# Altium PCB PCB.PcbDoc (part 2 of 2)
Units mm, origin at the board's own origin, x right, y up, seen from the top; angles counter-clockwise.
Board outline 68.58 x 53.34 mm, 2 copper layers (TOP, BOTTOM), stack 1.636 mm thick; 84 components, 64 nets, 302 pads, 163 vias.
Unrouted connection lines stored in the file: 1.
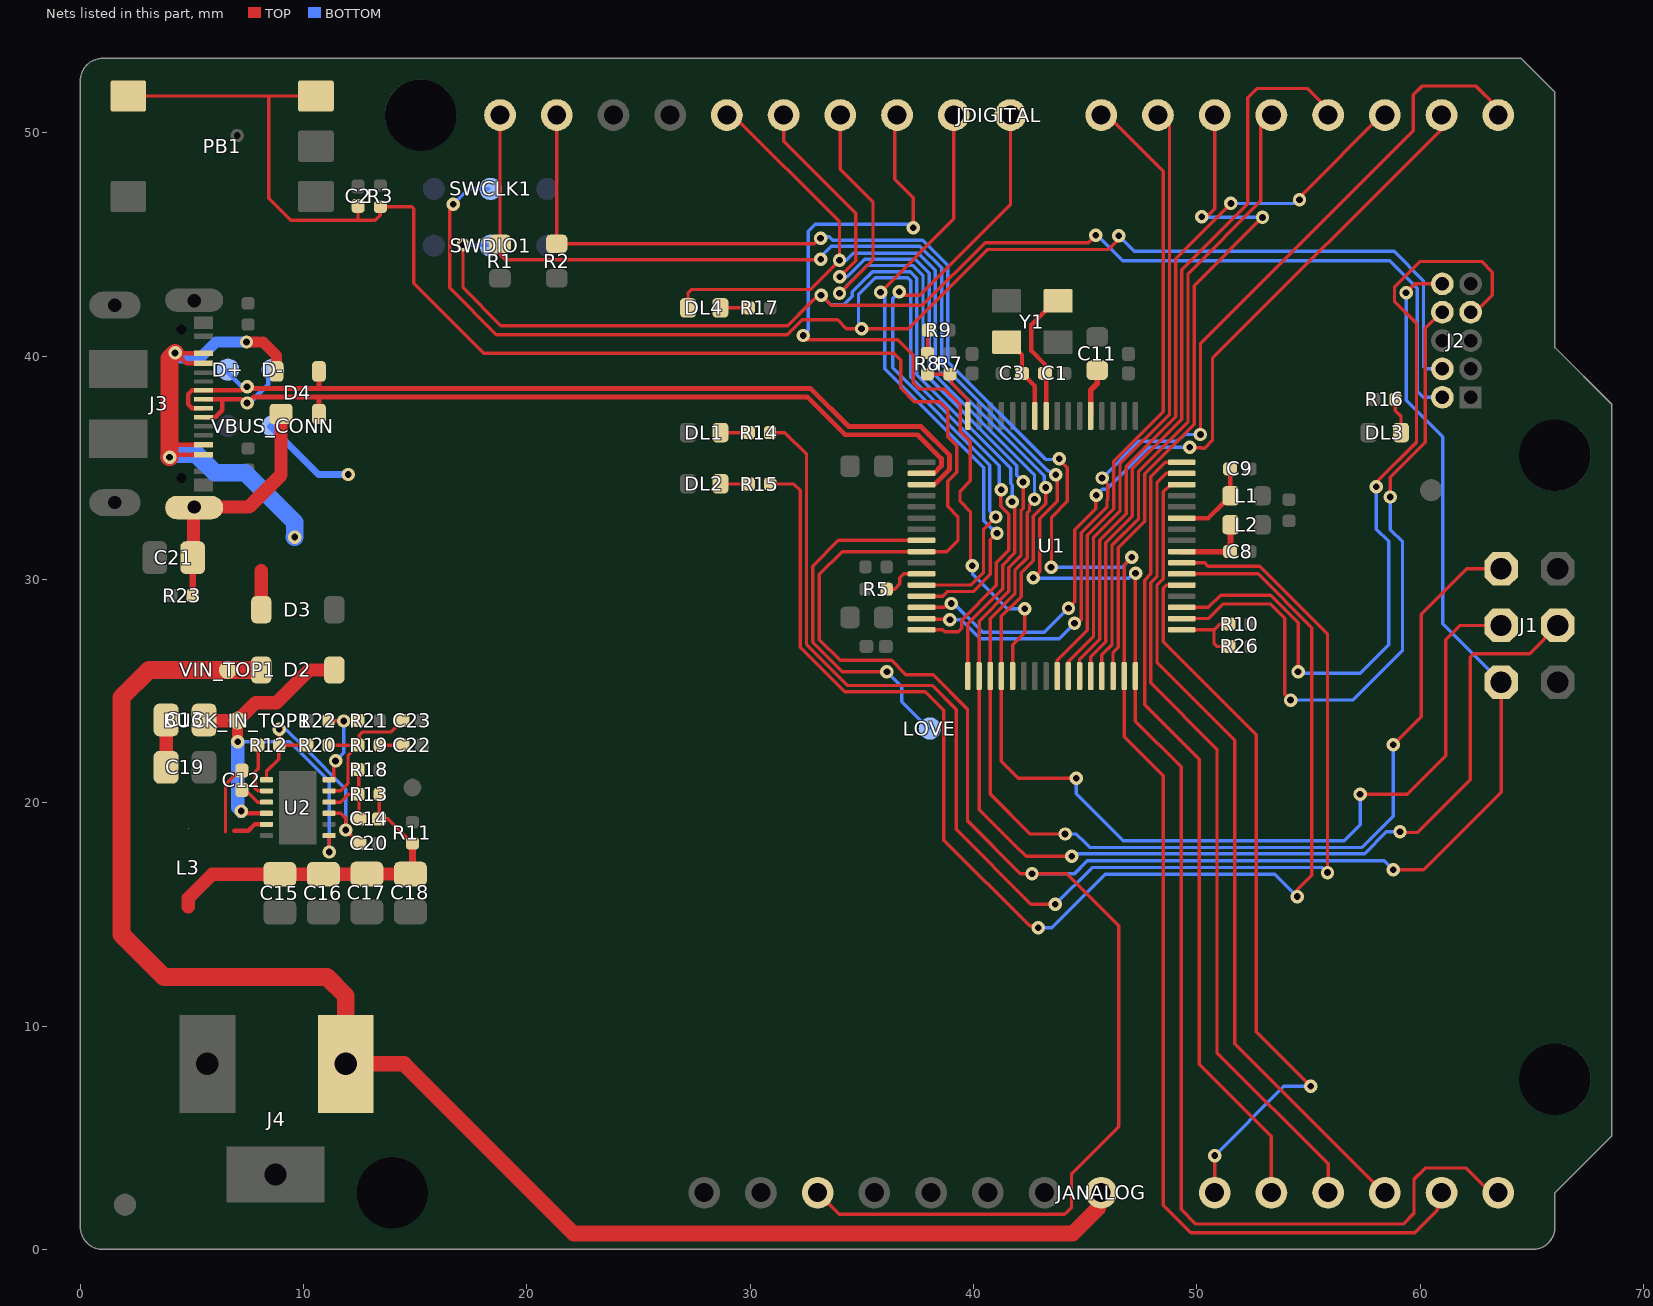
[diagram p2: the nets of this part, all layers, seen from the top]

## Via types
v1: diameter 0.6, hole 0.3, TOP to BOTTOM, tented both sides, 163 vias

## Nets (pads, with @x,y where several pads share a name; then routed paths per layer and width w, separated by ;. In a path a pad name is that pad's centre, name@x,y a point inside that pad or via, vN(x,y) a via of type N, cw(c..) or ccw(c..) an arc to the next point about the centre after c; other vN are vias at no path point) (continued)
NetBUCK_IN_TOP1_X: BUCK_IN_TOP1.X C13.2 D2.C U2.4 U2.7 | length 20.8
  TOP w0.15: U2.7@11.138,18.532 11.143,18.527 v1(11.143,17.796)
  TOP w0.2: v1(7.202,19.629) 7.299,19.532 U2.4@8.338,19.532
  TOP w0.5: BUCK_IN_TOP1.X@7.038,23.682 7.045,23.675 7.045,22.742 v1(7.052,22.735)
  TOP w0.6: C13.2@5.567,23.682 BUCK_IN_TOP1.X@6.984,23.682 ; BUCK_IN_TOP1.X@7.038,23.682 7.844,24.488 8.787,24.488 10.246,25.947 D2.C@11.373,25.947
  BOTTOM w0.15: v1(7.052,22.735) 9.371,22.735 11.143,20.964 v1(11.143,17.796) v1@11.056,17.71
  BOTTOM w0.6: v1(7.052,22.735) 7.052,19.779 v1(7.202,19.629)
NetC1_1: C1.1 U1.9 Y1.3 | length 5.9
  TOP w0.2: U1.9@43.25,37.325 43.25,39.184 C1.1@43.203,39.231 43.203,39.631 42.596,40.238 42.596,41.409 Y1.3@43.663,42.476
NetC3_1: C3.1 U1.10 Y1.1 | length 3.9
  TOP w0.2: Y1.1@41.487,40.626 41.612,40.626 42.173,40.066 C3.1@42.173,39.231 42.75,38.654 U1.10@42.75,37.325
NetC8_2: C8.2 L2.2 U1.56 | length 3.4
  TOP w0.25: U1.56@49.325,31.25 C8.2@51.493,31.25 ; C8.2@51.51,31.258 51.51,32.443 L2.2@51.518,32.45
NetC11_2: C11.2 U1.5 | length 2.2
  TOP w0.25: U1.5@45.25,37.325 45.25,38.478 45.538,38.766 C11.2@45.538,39.366
NetC12_1: C12.1 L3.1 U2.5 | length 4.4
  TOP w0.15: 6.5,18.7 6.5,20.804 6.945,21.249 7.029,21.249 7.038,21.258 C12.1@7.038,21.286
  TOP w0.2: 6.899,18.753 7.525,18.753 7.804,19.032 U2.5@8.338,19.032
NetC12_2: C12.2 U2.3 | length 1.5
  TOP w0.15: C12.2@7.038,20.572 7.411,20.572 7.951,20.032 U2.3@8.338,20.032
NetC13_1: C13.1 C19.2 | length 2.1
  TOP w0.6: C19.2@3.841,21.591 C13.1@3.841,23.708
NetC14_1: C14.1 R13.2 R18.2 U2.10 | length 3.7
  TOP w0.15: U2.10@11.138,20.032 11.656,20.032 12.005,20.381 12.462,20.381 R13.2@12.463,20.382 ; R18.2@12.463,21.482 R13.2@12.463,20.382 ; C14.1@12.503,19.282 12.483,19.302 12.483,20.362 R13.2@12.463,20.382
NetC14_2: C14.2 C15.2 C16.2 C17.2 C18.2 L3.2 R11.1 R13.1 | length 15.4
  TOP w0.15: C14.2@13.373,19.282 13.763,19.282 14.863,18.182 R11.1@14.873,18.182 ; C14.2@13.393,19.302 13.393,20.362 R13.1@13.413,20.382
  TOP w0.3: C18.2@14.784,16.812 14.873,16.9 R11.1@14.873,18.182
  TOP w0.5: C18.2@14.403,16.812 14.564,16.812 C18.2@14.869,17.117
  TOP w0.6: L3.2@4.836,15.349 4.836,15.721 5.912,16.797 8.501,16.797 8.509,16.804 10.886,16.804 C17.2@12.434,16.804 ; C17.2@12.434,16.812 C18.2@14.384,16.812
NetC20_1: C20.1 R12.2 R20.2 U2.1 U2.9 | length 12.2
  TOP w0.15: U2.1@8.338,21.032 8.338,21.408 8.886,21.956 8.886,22.555 R12.2@8.913,22.582 ; v1(8.908,23.294) 8.91,23.291 8.91,22.79 R12.2@8.908,22.787 ; R20.2@10.163,22.582 R12.2@9.113,22.582 ; U2.9@11.138,19.532 11.664,19.532 11.883,19.313 v1(11.883,18.781) 12.482,18.182 C20.1@12.503,18.182 ; R12.2@8.908,22.787 R12.2@9.113,22.582 ; R12.2@8.908,22.787 8.908,22.582 R12.2@8.913,22.582 ; R12.2@8.913,22.582 R12.2@9.113,22.582
  BOTTOM w0.15: v1(8.908,23.294) 9.204,23.294 10.066,22.432 11.883,20.616 v1(11.883,18.781)
NetC22_2: C22.2 R19.1 | length 1
  TOP w0.15: R19.1@13.413,22.582 C22.2@14.438,22.582
NetC23_2: C23.2 R19.2 R20.1 U2.11 | length 6.9
  TOP w0.15: R20.1@11.113,22.582 R19.2@12.463,22.582 ; U2.11@11.138,20.532 11.656,20.532 11.986,20.862 11.986,22.105 12.49,22.609 12.49,23.034 12.625,23.169 13.9,23.169 14.413,23.682 C23.2@14.438,23.682
NetDL1_C: DL1.C R14.2 | length 1.3
  TOP w0.15: DL1.C@28.665,36.576 R14.2@29.938,36.576
NetDL2_C: DL2.C R15.2 | length 1.3
  TOP w0.15: DL2.C@28.665,34.29 28.679,34.276 R15.2@29.945,34.276
NetDL3_C: DL3.C R16.2 | length 1.6
  TOP w0.15: R16.2@58.895,38.066 58.895,37.551 59.145,37.301 DL3.C@59.145,36.576
NetDL4_C: DL4.C R17.2 | length 1.3
  TOP w0.15: DL4.C@28.665,42.164 R17.2@29.945,42.164
NetR5_2: R5.2 U1.27 | length 2
  TOP w0.15: R5.2@36.113,29.566 36.463,29.566 36.699,29.802 36.699,30.079 36.87,30.25 U1.27@37.675,30.25
NetR7_1: R7.1 R8.2 U1.16 | length 3.2
  TOP w0.15: R8.2@37.938,39.191 R7.1@38.938,39.191 39.016,39.112 39.016,38.779 39.744,38.051 39.744,37.331 U1.16@39.75,37.325
NetR8_1: R8.1 R9.2 | length 1
  TOP w0.15: R8.1@37.938,40.141 37.95,40.154 37.95,41.154 R9.2@37.963,41.166
NetR10_1: R10.1 R26.2 U1.49 | length 3.6
  TOP w0.15: U1.49@49.325,27.75 50.773,27.75 ; R26.2@51.453,27 50.9,27 50.773,27.127 50.773,27.75 ; R10.1@51.453,28 51.023,28 50.773,27.75
NetR12_1: R12.1 U2.2 | length 2.5
  TOP w0.15: R12.1@7.963,22.582 7.963,21.525 7.834,21.396 7.834,20.635 7.937,20.532 U2.2@8.338,20.532
NetR21_2: R21.2 R22.2 U2.12 | length 4.1
  TOP w0.15: R22.2@11.113,23.682 11.123,23.671 11.781,23.671 v1(11.791,23.661) 11.802,23.671 12.452,23.671 R21.2@12.463,23.682 ; U2.12@11.138,21.032 11.304,21.032 11.344,21.072 v1@11.344,21.665
  BOTTOM w0.15: v1(11.432,21.875) 11.791,22.234 v1(11.791,23.661)
P000_AN00_AMP+_1: JANALOG.10 U1.64 | length 36.2
  TOP w0.15: U1.64@49.325,35.25 48.595,35.25 47.944,34.599 47.944,32.767 47.944,30.257 47.661,29.975 47.661,24.386 50.103,21.944 50.103,8.301 53.34,5.064 JANALOG.10@53.34,2.54
P001_AN01_AMP-_1: JANALOG.11 U1.63 | length 36.5
  TOP w0.15: U1.63@49.325,34.75 48.625,34.75 48.221,34.346 48.221,32.653 48.221,30.142 47.938,29.86 47.938,25.372 50.903,22.407 50.903,8.807 55.88,3.83 JANALOG.11@55.88,2.54
P002_AN02_AMPO_1: JANALOG.12 U1.62 | length 36.7
  TOP w0.15: U1.62@49.325,34.25 48.825,34.25 48.498,33.923 48.498,32.422 48.498,30.028 48.215,29.745 48.215,26.295 51.703,22.807 51.703,9.207 58.37,2.54 JANALOG.12@58.42,2.54
P012_1: R14.1 U1.55 | length 61.2
  TOP w0.15: R14.1@30.888,36.576 31.549,36.576 32.523,35.602 32.523,27.085 34.353,25.255 38.143,25.255 39.221,24.177 39.221,18.804 42.574,15.451 v1(43.668,15.451) ; U1.55@49.325,30.75 50.35,30.75 50.5,30.6 52.813,30.6 55.852,27.561 v1(55.852,16.874)
  BOTTOM w0.15: v1(43.668,15.451) 45.317,17.1 55.627,17.1 v1(55.852,16.874)
P013_1: R15.1 U1.54 | length 59.9
  TOP w0.15: R15.1@30.895,34.276 31.958,34.276 32.246,33.988 32.246,26.971 34.238,24.978 37.847,24.978 38.673,24.152 38.673,18.327 42.514,14.486 42.814,14.486 v1(42.9,14.4) ; U1.54@49.325,30.25 52.743,30.25 55.15,27.843 55.15,16.75 54.5,16.1 v1(54.5,15.8)
  BOTTOM w0.15: v1(42.9,14.4) 43.501,14.4 45.901,16.8 53.5,16.8 v1(54.5,15.8)
P014_AN09_DAC_1: JANALOG.9 U1.53 | length 33.2
  TOP w0.15: U1.53@49.325,29.75 48.625,29.75 48.492,29.617 48.492,27.218 52.655,23.055 52.655,9.745 v1(55.1,7.3) ; JANALOG.9@50.8,2.54 v1(50.8,4.2)
  BOTTOM w0.15: v1(50.8,4.2) 53.9,7.3 v1(55.1,7.3)
P100_AN22_SCL_1: JANALOG.14 JDIGITAL.18 R1.1 U1.48 | length 94.6
  TOP w0.15: JDIGITAL.18@18.796,51.054 R1.1@18.796,45.034 18.796,44.549 19.03,44.315 32.903,44.315 33.038,44.45 33.043,44.45 v1(33.156,44.337) ; v1(42.68,30.074) 42.96,30.354 42.96,32.724 43.744,33.508 43.744,34.633 v1(43.688,34.688) ; v1(47.259,30.282) 47.25,30.273 U1.48@47.25,25.675 47.25,23.66 49.303,21.607 49.303,1.793 49.961,1.135 59.239,1.135 59.727,1.623 59.727,3.145 60.226,3.644 62.062,3.644 63.166,2.54 JANALOG.14@63.5,2.54
  BOTTOM w0.15: v1(33.156,44.337) 33.156,44.446 33.633,44.923 37.602,44.923 38.571,43.954 38.571,43.382 38.571,39.636 43.332,34.875 43.38,34.875 43.566,34.688 v1(43.688,34.688) ; v1(42.68,30.074) 42.703,30.051 46.959,30.051 47.19,30.282 v1(47.259,30.282)
P101_AN21_SDA_1: JANALOG.13 JDIGITAL.17 R2.1 U1.47 | length 88.4
  TOP w0.15: JDIGITAL.17@21.336,51.054 R2.1@21.336,45.034 32.872,45.034 33.124,45.286 v1(33.15,45.286) ; v1(43.474,30.553) 43.494,30.573 43.494,32.788 44.201,33.495 44.201,35.002 43.834,35.37 v1(43.834,35.401) ; v1(47.09,30.992) 46.757,30.658 46.757,26.682 46.75,26.675 U1.47@46.75,25.675 46.75,22.96 48.503,21.207 48.503,1.966 49.719,0.75 59.76,0.75 60.764,1.754 60.764,2.344 JANALOG.13@60.96,2.54
  BOTTOM w0.15: v1(33.15,45.286) 33.215,45.35 33.55,45.35 33.7,45.2 37.716,45.2 38.848,44.069 38.848,43.497 38.848,39.751 43.224,35.375 43.808,35.375 v1(43.834,35.401) ; v1(43.474,30.553) 46.651,30.553 v1(47.09,30.992)
P102_SPI0_RSPCK_GPT2_B_CAN0_RX_1: JDIGITAL.6 U1.46 | length 31.2
  TOP w0.15: U1.46@46.25,25.675 46.25,26.734 46.48,26.964 46.48,31.411 47.667,32.598 47.667,32.882 47.667,34.728 49.886,36.947 49.886,43.16 v1(52.941,46.215) ; v1(50.228,46.241) 50.314,46.327 50.527,46.327 50.8,46.6 JDIGITAL.6@50.8,51.054
  BOTTOM w0.15: v1(50.228,46.241) 50.24,46.228 52.928,46.228 v1(52.941,46.215)
P103_SPI0_SSL_GPT2_A_CAN0_TX_1: JDIGITAL.5 U1.45 | length 28.4
  TOP w0.15: U1.45@45.75,25.675 45.75,26.626 46.203,27.079 46.203,31.526 47.39,32.713 47.39,32.997 47.39,34.843 49.609,37.062 49.609,43.7 52.865,46.956 52.865,48.614 52.865,50.417 JDIGITAL.5@53.34,50.892
P104_IRQ01_GPT1_B_1: JDIGITAL.4 U1.44 | length 33
  TOP w0.15: U1.44@45.25,25.675 45.25,26.541 45.926,27.217 45.926,31.641 47.113,32.828 47.113,33.111 47.113,34.957 49.332,37.176 49.332,43.879 52.289,46.836 52.289,51.575 52.705,51.99 54.944,51.99 JDIGITAL.4@55.88,51.054
P105_IRQ00_GPT1_A_1: JDIGITAL.3 U1.43 | length 32.7
  TOP w0.15: U1.43@44.75,25.675 44.75,26.433 45.649,27.331 45.649,31.755 46.836,32.943 46.836,33.226 46.836,35.072 49.055,37.291 49.055,44.359 51.528,46.831 v1(51.528,46.841) ; v1(54.6,47) 54.6,47.117 58.42,50.937 JDIGITAL.3@58.42,51.054
  BOTTOM w0.15: v1(51.528,46.841) 54.319,46.841 54.478,47 v1(54.6,47)
P106_GPT0_B_1: JDIGITAL.7 U1.42 | length 27.4
  TOP w0.15: U1.42@44.25,25.675 44.25,26.324 45.372,27.446 45.372,31.87 46.559,33.057 46.559,33.341 46.559,35.187 48.778,37.406 48.778,50.46 JDIGITAL.7@48.26,50.978
P107_GPT0_A_1: JDIGITAL.8 U1.41 | length 28.5
  TOP w0.15: U1.41@43.75,25.675 43.75,26.38 45.095,27.725 45.095,31.985 46.282,33.172 46.282,33.456 ; JDIGITAL.8@45.72,51.054 48.501,48.273 48.501,37.521 46.282,35.302 46.282,33.456
P108_SWDIO_1: J2.2 SWDIO1.X U1.33 | length 81.2
  TOP w0.15: v1(17.14,44.99) 17.14,43.064 18.838,41.366 31.677,41.366 32.604,42.293 33.042,42.731 v1(33.173,42.731) 33.631,42.274 34.422,42.274 37.714,42.274 40.516,45.076 45.142,45.076 v1(45.481,45.415) ; U1.33@39.75,25.675 39.75,28.028 41.303,29.581 41.303,30.643 41.852,31.192 41.852,33.238 41.727,33.363 v1(41.727,33.485)
  BOTTOM w0.15: v1(17.14,44.99) 17.156,44.974 18.272,44.974 SWDIO1.X@18.288,44.958 ; v1(33.173,42.731) 33.603,42.301 34.186,42.301 34.575,42.69 34.575,42.883 34.883,43.192 35.477,43.785 35.883,43.785 36.601,43.785 37.172,43.785 37.463,43.495 37.463,42.923 37.463,39.178 41.666,34.974 41.666,34.302 41.739,34.23 41.739,33.497 v1(41.727,33.485) ; v1(45.481,45.415) 45.546,45.415 45.596,45.364 46.687,44.274 58.649,44.274 59.874,43.048 59.874,38.429 60.144,38.16 J2.2@60.995,38.16
P109_SCI9_TXD_1: J1.4 JDIGITAL.12 U1.34 | length 74.8
  TOP w0.15: v1(34,42.825) 35.5,44.325 35.5,46.9 34.036,48.364 JDIGITAL.12@34.036,51.054 ; v1(42.221,34.369) 42.229,34.361 42.229,33.196 42.129,33.097 42.129,31.077 41.58,30.529 41.58,29.466 40.25,28.136 U1.34@40.25,25.675 40.25,19.694 41.204,18.74 41.844,18.1 41.853,18.1 42.353,17.6 v1(44.4,17.6) ; v1(59.1,18.7) 59.132,18.668 59.882,18.668 62.239,21.025 62.239,26.507 62.412,26.68 64.907,26.68 J1.4@66.167,27.94
  BOTTOM w0.15: v1(34,42.825) 34.644,43.469 35.237,44.062 35.998,44.062 36.715,44.062 37.287,44.062 37.74,43.61 37.74,43.038 37.74,39.292 41.943,35.089 41.943,34.659 42.221,34.381 v1(42.221,34.369) ; v1(44.4,17.6) 44.559,17.759 44.595,17.723 56.227,17.723 57.515,17.723 58.492,18.7 v1(59.1,18.7)
P110_SCI9_RXD_1: J1.1 JDIGITAL.13 U1.35 | length 73.4
  TOP w0.15: JDIGITAL.13@31.496,51.054 31.496,49.628 34.728,46.396 34.728,44.27 v1(34.013,43.555) ; v1(42.731,33.596) 42.731,33.516 42.506,33.291 42.506,33.081 42.406,32.982 42.406,30.963 41.857,30.414 41.857,29.351 40.75,28.244 U1.35@40.75,25.675 40.75,20.394 42.544,18.6 v1(44.1,18.6) ; v1(58.8,22.6) 60.052,23.852 60.052,28.452 62.08,30.48 J1.1@63.627,30.48
  BOTTOM w0.15: v1(34.013,43.555) 34.338,43.555 34.529,43.746 35.123,44.339 36.112,44.339 36.83,44.339 37.402,44.339 38.017,43.724 38.017,43.153 38.017,39.407 42.731,34.693 v1(42.731,33.596) ; v1(44.1,18.6) 44.6,18.6 45,18.2 45.01,18.2 45.21,18 57.4,18 58.8,19.4 v1(58.8,22.6)
P111_GPT3_A_1: DL4.A J1.3 JDIGITAL.14 U1.36 | length 78.6
  TOP w0.15: DL4.A@27.215,42.164 27.215,42.843 27.357,42.985 32.685,42.985 v1(34,44.3) 34,46.01 29.199,50.811 JDIGITAL.14@28.956,51.054 ; v1(43.233,34.121) 43.233,33.389 42.683,32.839 42.683,30.848 42.134,30.299 42.134,29.237 41.25,28.352 U1.36@41.25,25.675 41.25,21.85 42,21.1 v1(44.6,21.1) ; v1(57.313,20.376) 59.426,20.376 61.156,22.106 61.156,27.306 61.79,27.94 J1.3@63.627,27.94
  BOTTOM w0.15: v1(34,44.3) 34.3,44.3 34.616,44.616 35.132,44.616 36.227,44.616 36.945,44.616 37.516,44.616 38.294,43.839 38.294,43.267 38.294,39.522 43.173,34.642 43.173,34.182 v1(43.233,34.121) ; v1(44.6,21.1) 44.6,20.4 46.7,18.3 56.6,18.3 57.313,19.013 v1(57.313,20.376)
P112_GPT3_B_1: JDIGITAL.11 U1.37 | length 38.7
  TOP w0.15: v1(32.379,40.928) 32.575,40.732 36.614,40.732 37.3,40.046 37.3,38.8 37.569,38.531 38.699,38.531 39.405,37.825 39.405,36.612 39.857,36.16 39.857,34.413 39.396,33.953 39.396,33.504 39.863,33.037 39.863,30.921 39.863,30.7 v1(39.949,30.614) ; JDIGITAL.11@36.478,50.956 36.478,47.922 37.297,47.103 v1(37.297,45.753) ; U1.37@41.75,25.675 41.75,27.075 42.3,27.625 v1(42.3,28.692)
  BOTTOM w0.15: v1(32.379,40.928) 32.6,41.149 32.6,45.605 32.908,45.913 37.137,45.913 v1(37.297,45.753) ; v1(39.949,30.614) 39.971,30.592 39.971,30.239 41.517,28.692 v1(42.3,28.692)
P204_1: LOVE.X U1.24 | length 16
  TOP w0.15: v1(36.123,25.874) 34.126,25.874 32.8,27.2 32.8,30.6 33.95,31.75 U1.24@37.675,31.75
  BOTTOM w0.15: v1(36.123,25.874) 36.792,25.204 36.792,24.535 38.001,23.326 LOVE.X@38.045,23.326
P300_SWCLK_1: J2.4 SWCLK1.X U1.32 | length 82.8
  TOP w0.15: v1(16.7,46.8) 16.54,46.64 16.54,43.064 18.638,40.966 31.669,40.966 32.329,41.626 33.912,41.626 34.304,41.234 v1(34.987,41.234) 37.074,41.234 40.616,44.776 46.044,44.776 46.5,45.232 v1(46.5,45.4) ; U1.32@37.675,27.75 38.615,27.75 38.71,27.655 39.316,27.655 39.473,27.812 39.473,28.179 41.026,29.733 41.026,30.758 41.575,31.307 41.575,32.926 41.225,33.277 41.225,34.01 v1(41.237,34.022)
  BOTTOM w0.15: v1(16.7,46.8) 17.394,47.494 18.284,47.494 SWCLK1.X@18.288,47.498 ; v1(34.987,41.234) 34.852,41.369 34.852,42.769 35.591,43.508 37.058,43.508 37.186,43.38 37.186,39.063 41.16,35.088 41.16,34.098 v1(41.237,34.022) ; v1(46.5,45.4) 47.202,44.698 58.833,44.698 60.151,43.379 60.151,39.549 60.27,39.43 J2.4@60.995,39.43 ; J2.4@61.093,39.665 61.126,39.665 J2.4@61.361,39.43
P301_SCI2_RXD_1: JDIGITAL.1 U1.31 | length 43.4
  TOP w0.15: U1.31@37.675,28.25 37.703,28.222 38.917,28.222 v1(38.945,28.195) ; v1(44.524,28.041) 44.658,28.041 44.818,28.201 44.818,32.1 45.98,33.262 45.98,33.546 46.005,33.57 46.005,34.26 45.758,34.508 v1(45.758,34.543) ; v1(50.163,36.491) 50.163,40.563 59.7,50.1 59.7,51.7 60.1,52.1 62.5,52.1 JDIGITAL.1@63.4,51.2
  BOTTOM w0.15: v1(38.945,28.195) 39.46,28.195 40.302,27.354 43.837,27.354 v1(44.524,28.041) ; v1(45.758,34.543) 47.409,36.195 49.134,36.195 49.43,36.491 v1(50.163,36.491)
P302_SCI2_TXD_1: JDIGITAL.2 U1.30 | length 38.5
  TOP w0.15: U1.30@37.675,28.75 38.703,28.75 38.878,28.925 v1(39,28.925) ; v1(44.252,28.716) 44.256,28.716 44.541,29.001 44.541,32.226 45.478,33.163 45.478,33.753 v1(45.503,33.778) ; v1(49.686,35.918) 49.71,35.893 50.211,35.893 50.223,35.881 50.348,35.881 50.7,36.233 50.7,39.9 60.96,50.16 JDIGITAL.2@60.96,51.054
  BOTTOM w0.15: v1(39,28.925) 39.122,28.925 40.416,27.631 43.171,27.631 44.252,28.712 v1(44.252,28.716) ; v1(45.503,33.778) 45.507,33.778 45.77,34.041 45.966,34.041 47.842,35.918 v1(49.686,35.918)
P303_GPT7_B_1: JDIGITAL.10 U1.29 | length 28
  TOP w0.15: v1(35.838,42.87) 39.116,46.147 JDIGITAL.10@39.116,51.054 ; U1.29@37.675,29.25 38.615,29.25 38.825,29.46 39.984,29.46 40.749,30.225 40.749,31.77 v1(41.051,32.072)
  BOTTOM w0.15: v1(35.838,42.87) 36.027,42.681 36.027,39.438 40.457,35.008 40.457,32.625 40.787,32.294 40.828,32.294 v1(41.051,32.072)
P304_GPT7_A_1: JDIGITAL.9 U1.28 | length 28.8
  TOP w0.15: v1(36.676,42.88) 36.825,42.731 37.6,42.731 41.656,46.786 JDIGITAL.9@41.656,51.054 ; U1.28@37.675,29.75 39.882,29.75 40.451,30.318 40.451,32.252 v1(40.995,32.796)
  BOTTOM w0.15: v1(36.676,42.88) 36.379,42.583 36.379,41.771 36.379,39.478 40.734,35.123 40.734,33.066 40.995,32.804 v1(40.995,32.796)
P501_SCI1_TXD_1: J2.8 U1.50 | length 31.2
  TOP w0.15: U1.50@49.325,28.25 50.519,28.25 51.169,28.9 53.31,28.9 53.936,28.273 53.936,24.867 54.2,24.603 v1(54.2,24.6) ; v1(58.665,33.693) 58.665,34.579 60.223,36.137 60.223,41.251 J2.8@60.942,41.97
  BOTTOM w0.15: v1(54.2,24.6) 56.986,24.6 59.214,26.828 59.214,31.686 58.665,32.235 v1(58.665,33.693)
P502_SCI1_RXD_1: J2.7 U1.51 | length 37.6
  TOP w0.15: U1.51@49.325,28.75 50.519,28.75 51.069,29.3 53.302,29.3 54.536,28.065 v1(54.536,25.868) ; v1(58.042,34.158) 58.129,34.244 58.129,34.434 59.839,36.145 59.839,41.467 58.852,42.454 58.852,43.095 59.999,44.241 62.758,44.241 63.229,43.77 63.229,42.729 62.4,41.9 J2.7@62.187,41.9
  BOTTOM w0.15: v1(54.536,25.868) 54.605,25.8 57.324,25.8 58.591,27.067 58.591,31.709 58.042,32.258 v1(58.042,34.158)
R\E\S\E\T\_1: C2.1 J1.5 J2.10 JANALOG.3 PB1.3 PB1.4 R3.1 U1.25 | length 163.3
  TOP w0.15: PB1.4@2.15,51.653 8.434,51.653 ; PB1.3@10.55,51.653 8.434,51.653 ; C2.1@12.438,46.731 12.434,46.727 12.434,46.09 ; JANALOG.3@33.02,2.54 33.994,1.567 44.077,1.567 44.389,1.879 44.389,3.389 46.5,5.5 46.5,14.5 44.177,16.823 v1(42.619,16.823) 42.102,16.823 39.731,19.194 39.731,24.193 38.187,25.738 36.968,25.738 36.33,26.376 34.024,26.376 33.098,27.302 33.098,30.226 34.122,31.25 U1.25@37.675,31.25 38.81,31.25 39.303,31.743 39.303,32.813 38.842,33.273 38.842,34.404 39.244,34.806 39.244,35.989 38.851,36.383 38.851,37.595 38.48,37.966 37.35,37.966 36.735,38.581 36.735,39.827 36.425,40.137 18.063,40.137 14.94,43.26 14.94,46.603 14.852,46.691 R3.1@13.438,46.691 13.438,46.316 13.212,46.09 12.434,46.09 ; v1(58.8,17) 60.154,17 63.627,20.473 J1.5@63.627,25.4 ; v1(59.372,42.841) 59.772,43.24 J2.10@60.995,43.24 ; 8.434,51.653 8.434,47.078 9.422,46.09 12.434,46.09
  BOTTOM w0.15: v1(42.619,16.823) 44.523,16.823 45.1,17.4 58.4,17.4 v1(58.8,17) ; v1(59.372,42.841) 59.372,38.024 61.012,36.384 61.012,28.015 J1.5@63.627,25.4
SHIELD2_1: C21.2 D4.1 J3.SHIELD2 R23.2 | length 11.2
  TOP w0.3: R23.2@5.034,29.278 C21.2@5.034,30.978
  TOP w0.6: C21.2@5.034,30.978 5.067,31.012 5.067,33.213 J3.SHIELD2@5.1,33.246 7.552,33.246 8.988,34.681 D4.1@8.988,37.411
  BOTTOM w0.6: J3.SHIELD2@5.1,33.246 J3.SHIELD2@5.125,33.221
USB_D_1_N: D4.2 D-.X J3.A7 J3.B7 U1.18 | length 39.6
  TOP w0.2: J3.A7@5.525,37.266 6.044,37.266 6.353,37.575 6.353,38.066 ; J3.B7@5.525,38.066 6.353,38.066 ; v1(7.469,37.904) 7.36,37.904 7.197,38.067 6.753,38.067 6.752,38.066 6.353,38.066
  TOP w0.22: v1(7.469,37.904) 7.501,37.904 7.775,38.177 9.338,38.177 10.49,38.177 10.69,38.177 ; D4.2@10.69,37.414 10.69,38.177 ; U1.18@37.675,34.75 37.69,34.765 38.239,34.765 38.562,35.088 38.562,35.412 37.49,36.484 34.253,36.484 32.559,38.177 10.69,38.177
  BOTTOM w0.2: v1(7.469,37.904) 7.545,37.98 7.656,37.98 8.426,38.75 8.426,39.061 D-.X@8.481,39.116
USB_D_1_P: D4.3 D+.X J3.A6 J3.B6 U1.19 | length 40.9
  TOP w0.2: J3.B6@5.525,37.666 5,37.666 4.824,37.842 4.824,38.29 5,38.466 J3.A6@5.525,38.466 6.552,38.466 6.553,38.467 7.197,38.467 7.36,38.631 v1(7.469,38.631)
  TOP w0.22: v1(7.469,38.631) 7.541,38.558 7.777,38.558 7.787,38.547 9.184,38.547 10.487,38.547 10.687,38.547 ; D4.3@10.687,39.32 10.687,38.547 ; U1.19@37.675,34.25 37.69,34.265 38.262,34.265 38.932,34.935 38.932,35.565 37.643,36.854 34.406,36.854 32.712,38.547 10.687,38.547
  BOTTOM w0.2: D+.X@6.52,39.35 7.163,38.707 7.392,38.707 v1(7.469,38.631)
VIN: D2.A J4.1 JANALOG.8 VIN_TOP1.X | length 69.7
  TOP w0.7: J4.1@11.89,8.306 14.494,8.306 22.091,0.709 44.448,0.709 45.582,1.843 45.582,2.402 JANALOG.8@45.72,2.54
  TOP w0.8: D2.A@8.103,25.947 VIN_TOP1.X@6.603,25.947 3.071,25.947 1.846,24.722 1.846,14.104 3.75,12.2 11.05,12.2 11.89,11.36 J4.1@11.89,8.306
VREFH0_1: C9.1 L1.2 U1.59 | length 3.8
  TOP w0.2: U1.59@49.325,32.75 50.517,32.75 51.183,33.415 51.193,33.415 51.518,33.739 L1.2@51.518,33.75 51.505,33.763 51.505,34.886 C9.1@51.489,34.902
VUSB: D3.A D4.4 J3.A4 J3.A9 J3.B4 J3.B9 VBUS_CONN.X | length 30
  TOP w0.2: v1(3.998,35.475) 4.114,35.591 J3.A9@5.525,35.591 ; 4,36.1 4.059,36.041 J3.B4@5.525,36.041 ; v1(4.244,40.146) 4.267,40.124 v1@4.284,40.141 ; J3.B9@5.525,39.691 4.734,39.691 4.5,39.925 v1@4.284,40.141 ; J3.A4@5.525,40.141 v1@4.284,40.141
  TOP w0.5: v1(7.443,40.637) 7.977,40.637 ; 8.177,40.637 8.788,40.026 D4.4@8.788,39.321
  TOP w0.6: D3.A@8.103,28.647 8.103,30.397
  TOP w0.8: v1(3.998,35.475) 4,35.477 4,36.1 4,39.903 v1(4.244,40.146)
  BOTTOM w0.3: VBUS_CONN.X@8.52,36.85 10.67,34.7 v1(12,34.7)
  BOTTOM w0.5: v1(4.244,40.146) 4.465,39.925 5.366,39.925 6.078,40.637 v1(7.443,40.637)
  BOTTOM w0.8: v1(3.998,35.475) 4.145,35.621 5.185,35.621 6.027,34.779 7.384,34.779 9.6,32.563 v1(9.6,31.9)
pads on no net: Fiducial_1.1 Fiducial_2.1 J2.6 J3.A8 J3.B8 J3.FIXING J3.SHIELD1 J3.SHIELD3 J3.SHIELD4 U1.1 U1.2 U1.3 U1.6 U1.7 U1.12 U1.13 U1.14 U1.15 U1.22 U1.23 U1.38 U1.52 U1.58 U1.60 U1.61 U2.8 Y1.2 Y1.4

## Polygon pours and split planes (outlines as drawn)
GND on BOTTOM "GND_L02_P034" (solid, remove dead copper, pour order 34): 0,1 0,52.34 cw(c1,52.34) 1,53.34 64.516,53.34 66.04,51.816 66.04,40.386 68.58,37.846 68.58,5.08 66.04,2.54 66.04,1 cw(c65.04,1) 65.04,0 1,0 cw(c1,1)
+5V on BOTTOM "+5V_L02_P033" (solid, remove dead copper, pour order 33): 36.206,26.498 36.206,25.615 36.872,24.949 39.239,24.949 39.8,24.406 39.8,22.6 38.6,21.4 35.67,21.4 35.402,21.132 35.402,20.597 35.782,20.217 40.017,20.217 43.4,23.6 43.4,24.9 42.035,26.265 38.505,26.265 38.2,26.57 37.604,27.166 36.875,27.166
GND on TOP "GND_L01_P041" (solid, remove dead copper, pour order 41): 0,1 0,52.34 cw(c1,52.34) 1,53.34 64.516,53.34 66.04,51.816 66.04,40.386 68.58,37.846 68.58,5.08 66.04,2.54 66.04,1 cw(c65.04,1) 65.04,0 1,0 cw(c1,1)
+5V on TOP "+5V_L01_P040" (solid, remove dead copper, pour order 40): 31.178,1.747 31.178,4.722 31.636,5.08 36.414,5.08 36.992,4.502 37.003,1.747 38.803,1.747 39.103,2.047 39.103,14.897 37.443,16.557 37.443,20.76 36.903,21.3 35.524,21.3 29.15,21.3 22.303,28.147 14.253,28.147 12.997,29.403 10.803,29.403 10.803,27.854 12.046,27.854 14.253,25.647 16.903,25.647 17.403,25.147 17.403,22.247 16.603,21.447 14.603,21.447 14.103,20.947 14.103,19.007 14.463,18.647 15.903,18.647 19.003,15.547 24.703,15.547 26.456,17.3 35.04,17.3 35.871,16.469 35.871,7.285 34.9,6.314 30.845,6.314 29.7,5.169 29.7,1.747
VUSB on TOP "VUSB_L01_P039" (solid, remove dead copper, pour order 39): 7.6,29.5 7.6,31.1 11.61,35.11 12.4,35.11 12.6,34.9 12.6,33.4 8.7,29.5

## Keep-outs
TOP:
  region: 0.06,41.191 3.66,41.191 6.96,41.981 6.96,42.988 6.255,43.651 0.06,43.651
  region: 0.06,34.541 3.66,34.541 5.16,33.681 3.56,32.081 0.06,32.081
  region: 7.1,34 7.1,33.121 6.56,32.581 6.16,32.181 6.16,29.03 5.808,28.7 4.755,28.7 4.751,29.358 3.4,30.055 3.4,34
BOTTOM:
  region: 0.06,41.191 3.66,41.191 6.96,41.981 6.96,42.988 6.255,43.651 0.06,43.651
  region: 7.1,34 7.1,33.121 6.56,32.581 6.16,32.181 6.16,32.078 3.4,32.078 3.4,34
  region: 0.06,34.541 3.66,34.541 5.16,33.681 3.56,32.081 0.06,32.081

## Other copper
TOP:
  region net NetC12_1: 6.677,19.023 7.937,19.021 7.016,18.1 4.238,18.1 4.238,19.023
  pour cut-out: 773 vertices and 0 holes, not listed, extent 0.99,7.121 3.371,9.489
  region: 585 vertices and 2 holes, not listed, extent 1.245,7.854 3.13,8.754
BOTTOM:
  region net P204_1: 1461 vertices and 0 holes, not listed, extent 36.796,22.053 39.253,24.425
  pour cut-out: 773 vertices and 0 holes, not listed, extent 1.002,7.121 3.383,9.489
  pour cut-out: 773 vertices and 0 holes, not listed, extent 0.99,7.121 3.371,9.489
  pour cut-out: 773 vertices and 0 holes, not listed, extent 0.99,7.121 3.371,9.489
  pour cut-out: 773 vertices and 0 holes, not listed, extent 0.99,7.121 3.371,9.489
  region: 241 vertices and 0 holes, not listed, extent 6.363,46.342 6.985,47.605
  region: 250 vertices and 0 holes, not listed, extent 4.108,45.171 5.325,45.859
  region: 1833 vertices and 1 holes, not listed, extent 2.686,46.104 7.428,50.926
  text "1.4" at 9.4,0.3 h1
  text "V" at 10.7,0.3 h1

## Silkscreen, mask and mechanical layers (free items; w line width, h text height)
Top Overlay:
  drawing of 174 lines, arcs and shapes, not listed
Bottom Overlay:
  drawing of 138 lines, arcs and shapes, not listed
Top Solder:
  drawing of 4 lines, arcs and shapes, not listed
Bottom Solder:
  region: 1461 vertices and 0 holes, not listed, extent 36.796,22.053 39.253,24.425
Route Tool Path:
  lines w2: -1,6 -1,1 ccw(c1,1) 1,-1 65.04,-1 ccw(c65.04,1) 67.04,1 67.04,2.126 69.287,4.373 ; -1,10 -1,35.866 ; -1,39.866 -1,52.34 cw(c1,52.34) 1,54.34 64.516,54.34 ; 69.58,19.463 69.58,5.08 ; 69.58,23.463 69.58,37.846 ; 64.516,54.34 cw(c64.516,53.34) 65.223,54.047 ; 64.516,54.34 cw(c64.516,53.34) 65.223,54.047 ; 65.223,54.047 66.747,52.523 ; 66.747,52.523 cw(c66.04,51.816) 67.04,51.816 ; 66.747,52.523 cw(c66.04,51.816) 67.04,51.816 ; 67.04,51.816 67.04,40.8 69.287,38.553 ; 69.287,4.373 ccw(c68.58,5.08) 69.58,5.08 ; 69.287,4.373 ccw(c68.58,5.08) 69.58,5.08 ; 69.287,38.553 cw(c68.58,37.846) 69.58,37.846 ; 69.287,38.553 cw(c68.58,37.846) 69.58,37.846
Board:
  the board outline again, w0.127
TestPointsHeaders:
  drawing of 286 lines, arcs and shapes, not listed
  text "SCL" at 18.263,52.31 h0.4
  text "SDA" at 20.803,52.31 h0.4
  text "AREF" at 23.143,52.31 h0.4
  text "GND" at 25.883,52.31 h0.4
  text "13" at 28.656,52.31 h0.4
  text "12" at 31.196,52.31 h0.4
  text "11" at 33.803,52.31 h0.4
  text "10" at 36.276,52.31 h0.4
  text "9" at 38.983,52.31 h0.4
  text "8" at 41.523,52.31 h0.4
  text "7" at 45.587,52.31 h0.4
  text "6" at 48.127,52.31 h0.4
  text "5" at 50.667,52.31 h0.4
  text "4" at 53.207,52.31 h0.4
  text "3" at 55.747,52.31 h0.4
  text "2" at 58.287,52.31 h0.4
  text "1 TX" at 60.26,52.31 h0.4
  text "0 RX" at 62.767,52.31 h0.4
  text "SCL" at 19.329,51.71 h0.4
  text "SDA" at 21.869,51.71 h0.4
  text "AREF" at 24.609,51.71 h0.4
  text "GND" at 26.949,51.71 h0.4
  text "13" at 29.256,51.71 h0.4
  text "12" at 31.796,51.71 h0.4
  text "11" at 34.269,51.71 h0.4
  text "10" at 36.876,51.71 h0.4
  text "9" at 39.249,51.71 h0.4
  text "8" at 41.789,51.71 h0.4
  text "7" at 45.853,51.71 h0.4
  text "6" at 48.393,51.71 h0.4
  text "5" at 50.933,51.71 h0.4
  text "4" at 53.473,51.71 h0.4
  text "3" at 56.013,51.71 h0.4
  text "2" at 58.553,51.71 h0.4
  text "1 TX" at 61.66,51.71 h0.4
  text "0 RX" at 64.233,51.71 h0.4
  text "3.2mm" at 14.34,51.654 h0.4
  text "3.2mm" at 16.14,49.554 h0.4
  text "SWCLK" at 16.439,48.744 h0.4
  text "SWCLK" at 18.327,48.186 h0.4
  text "NC" at 22.037,47.682 h0.4
  text "nRST" at 13.271,47.542 h0.4
  text "NC" at 22.737,47.082 h0.4
  text "nRST" at 14.749,47.016 h0.4
  text "5V" at 22.036,45.143 h0.4
  text "GND" at 13.687,45.058 h0.4
  text "5V" at 22.736,44.543 h0.4
  text "GND" at 14.749,44.476 h0.4
  text "SWDIO" at 16.899,43.71 h0.4
  text "SWDIO" at 18.787,43.152 h0.4
  text "DP" at 4.934,39.55 h0.4
  text "DN" at 9.634,39.55 h0.4
  text "DP" at 5.634,38.95 h0.4
  text "DN" at 10.334,38.95 h0.4
  text "GND" at 4.534,36.925 h0.4
  text "VCONN" at 9.653,36.91 h0.4
  text "3.2mm" at 65.14,36.414 h0.4
  text "GND" at 5.615,36.325 h0.4
  text "VCONN" at 11.534,36.31 h0.4
  text "3.2mm" at 66.94,34.314 h0.4
  text "MISO" at 61.687,29.649 h0.4
  text "5V" at 66.554,29.649 h0.4
  text "MISO" at 63.083,29.03 h0.4
  text "5V" at 67.216,29.03 h0.4
  text "SCK" at 61.687,27.109 h0.4
  text "MOSI" at 66.554,27.109 h0.4
  text "SCK" at 62.749,26.49 h0.4
  text "MOSI" at 67.883,26.49 h0.4
  text "nRST" at 61.687,24.569 h0.4
  text "GND" at 66.554,24.569 h0.4
  text "GND" at 67.616,23.987 h0.4
  text "nRST" at 63.149,23.95 h0.4
  text "3.2mm" at 65.14,8.474 h0.4
  text "GND" at 2.867,8.45 h0.4
  text "VIN" at 13.5,8.45 h0.4
  text "GND" at 3.933,7.85 h0.4
  text "VIN" at 14.5,7.85 h0.4
  text "3.2mm" at 66.94,6.374 h0.4
  text "NC" at 27.607,4.05 h0.4
  text "IOREF" at 29.58,4.05 h0.4
  text "nRST" at 32.287,4.05 h0.4
  text "3V3" at 35.027,4.05 h0.4
  text "5V" at 37.767,4.05 h0.4
  text "GND" at 40.107,4.05 h0.4
  text "GND" at 42.647,4.05 h0.4
  text "VIN" at 45.22,4.05 h0.4
  text "A0" at 50.467,4.05 h0.4
  text "A1" at 53.073,4.05 h0.4
  text "A2" at 55.547,4.05 h0.4
  text "A3" at 58.087,4.05 h0.4
  text "A4 SDA" at 59.827,4.008 h0.4
  text "A5 SCL" at 63.067,4.008 h0.4
  text "GND" at 4.967,3.45 h0.4
  text "NC" at 28.273,3.45 h0.4
  text "IOREF" at 31.38,3.45 h0.4
  text "nRST" at 33.753,3.45 h0.4
  text "3V3" at 36.093,3.45 h0.4
  text "5V" at 38.433,3.45 h0.4
  text "GND" at 41.173,3.45 h0.4
  text "GND" at 43.713,3.45 h0.4
  text "VIN" at 46.22,3.45 h0.4
  text "A0" at 51.133,3.45 h0.4
  text "A1" at 53.607,3.45 h0.4
  text "A2" at 56.213,3.45 h0.4
  text "A3" at 58.753,3.45 h0.4
  text "A4 SDA" at 62.093,3.426 h0.4
  text "A5 SCL" at 65.333,3.426 h0.4
  text "3.2mm" at 13.07,3.394 h0.4
  text "GND" at 6.033,2.85 h0.4
  text "3.2mm" at 14.87,1.294 h0.4
Measurements:
  the board outline again, w0.127
Board_Kicad:
  lines w0.05: 26.88,2.54 27.94,2.54 ; 27.94,1.48 27.94,2.54 ; 27.94,3.6 27.94,2.54 ; 29,2.54 27.94,2.54
  lines w0.127: 0,1 ccw(c1,1) 1,0 65.04,0 ccw(c65.04,1) 66.04,1 66.04,2.54 68.58,5.08 68.58,37.846 66.04,40.386 66.04,51.816 64.516,53.34 1,53.34 ccw(c1,52.34) 0,52.34 0,1
POGO_NORI:
  drawing of 200 lines, arcs and shapes, not listed
UNOR3_holes:
  drawing of 172 lines, arcs and shapes, not listed

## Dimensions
66.04,53.34 to 68.58,53.34 on Mechanical 16
68.58,5.08 to 68.694,37.846 on Mechanical 16
66.04,0 to 64.516,53.34 on Mechanical 16
66.04,0 to 66.04,51.816 on Mechanical 16
66.04,0 to 66.04,40.386 on Mechanical 16
66.04,0 to 68.58,37.846 on Mechanical 16
66.04,0 to 68.58,5.08 on Mechanical 16
66.04,0 to 66.04,2.54 on Mechanical 16
0,53.34 to 68.58,37.846 on Mechanical 16
0,53.34 to 66.04,53.34 on Mechanical 16
0,53.34 to 64.516,53.34 on Mechanical 16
